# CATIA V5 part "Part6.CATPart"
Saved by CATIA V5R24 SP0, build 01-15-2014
Part number: lado de trás
Bounding box of the stored display mesh (mm): x 0 to 3, y -197 to 197, z -225 to 225
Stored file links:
  C:\Users\Fatec\Desktop\Maquina componentes catia\Part6.CATPart
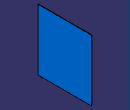
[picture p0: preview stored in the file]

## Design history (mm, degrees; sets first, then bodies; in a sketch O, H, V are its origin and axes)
Body1 (main body)
  Sketch1 on yz-plane, origin (0, 0, 0), H (0, 1, 0), V (0, 0, 1)
    line L1 (-197, 225) -> (197, 225)
    line L2 (197, 225) -> (197, -225)
    line L3 (197, -225) -> (-197, -225)
    line L4 (-197, -225) -> (-197, 225)
    length L4 = 450
    length L3 = 394
    horizontal: L1 H, L3 H
    vertical: L2 V, L4 V
    symmetry: L4 L2 V, L3 L1 H
  Pad1: profile Sketch1, direction (1, 0, 0), length 3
